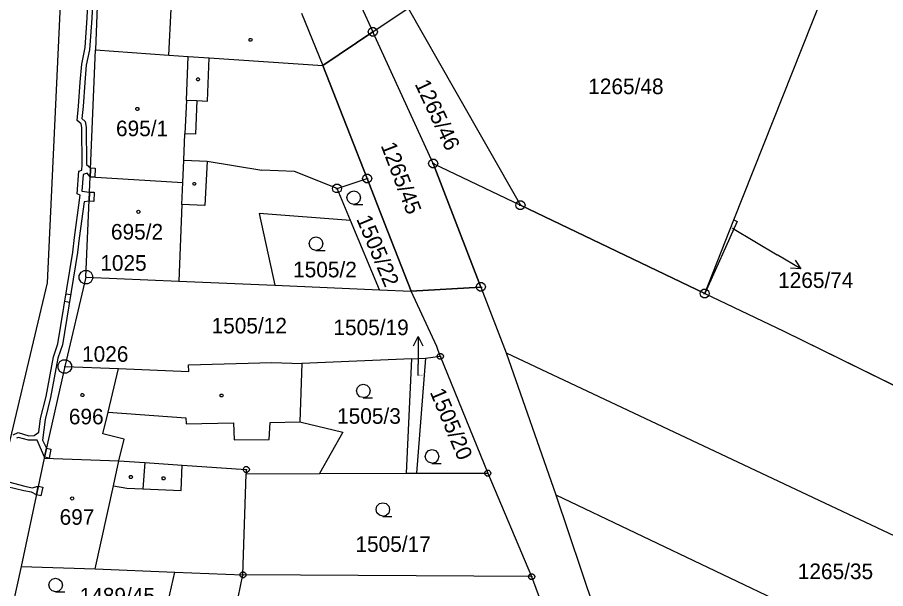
# Model space of a CAD drawing. Extents: x -779618 to -776429, y -1144546 to -1143350.
# Drawn here: x -777317.2 to -777222.5, y -1143978.4 to -1143916.1 of the extents above; entities that cross this region are included whole.
import ezdxf

# ---------------------------------------------------------------- set-up
doc = ezdxf.new("R2010")
doc.units = 0
for name, color, linetype in [('1', 7, 'Continuous'), ('11', 7, 'Continuous'), ('12', 7, 'Continuous'), ('13', 7, 'Continuous'), ('2', 7, 'Continuous'), ('3', 7, 'Continuous'), ('4', 7, 'Continuous'), ('5', 7, 'Continuous'), ('7', 7, 'Continuous'), ('8', 7, 'Continuous')]:
    doc.layers.add(name, color=color, linetype=linetype)

msp = doc.modelspace()

# ---------------------------------------------------------------- linework, layer by layer
at = {"layer": '1'}
for p, q in [((-777311.09, -1143883.18), (-777313.96, -1143945.06)), ((-777307.94, -1143898.78), (-777308.68, -1143919.63)), ((-777239.05, -1143938.18), (-777226.25, -1143905.92)), ((-777279.72, -1143914.89), (-777278.44, -1143917.67)), ((-777278.44, -1143917.67), (-777274.6, -1143915.07)), ((-777286.22, -1143915.64), (-777283.88, -1143921.35)), ((-777283.88, -1143921.35), (-777278.44, -1143917.67)), ((-777271.84, -1143932.03), (-777278.44, -1143917.67)), ((-777309.27, -1143933.48), (-777308.68, -1143919.63)), ((-777308.68, -1143919.63), (-777300.69, -1143920.2)), ((-777300.69, -1143920.2), (-777298.57, -1143920.35)), ((-777298.57, -1143920.35), (-777296.28, -1143920.51)), ((-777296.28, -1143920.51), (-777283.88, -1143921.35)), ((-777279.06, -1143933.68), (-777283.88, -1143921.35)), ((-777299.16, -1143934.11), (-777299.05, -1143931.67)), ((-777299.05, -1143931.67), (-777296.52, -1143931.78)), ((-777296.52, -1143931.78), (-777290.55, -1143932.77)), ((-777271.84, -1143932.03), (-777266.65, -1143945.51)), ((-777271.84, -1143932.03), (-777262.34, -1143936.58)), ((-777287, -1143932.91), (-777290.55, -1143932.77)), ((-777282.34, -1143934.75), (-777287, -1143932.91)), ((-777309.73, -1143944.43), (-777309.27, -1143933.48)), ((-777309.27, -1143933.48), (-777299.16, -1143934.11)), ((-777282.34, -1143934.75), (-777279.06, -1143933.68)), ((-777277.16, -1143938.54), (-777279.06, -1143933.68)), ((-777280.87, -1143938.26), (-777282.34, -1143934.75)), ((-777242.24, -1143946.21), (-777262.34, -1143936.58)), ((-777280.87, -1143938.26), (-777290.83, -1143937.5)), ((-777290.83, -1143937.5), (-777289.12, -1143945.32)), ((-777277.71, -1143945.82), (-777280.87, -1143938.26)), ((-777274.26, -1143945.97), (-777277.16, -1143938.54)), ((-777242.24, -1143946.21), (-777239.05, -1143938.18)), ((-777238.7, -1143938.36), (-777242.24, -1143946.21)), ((-777239.05, -1143938.18), (-777238.7, -1143938.36)), ((-777309.73, -1143944.43), (-777312.04, -1143954.18)), ((-777309.73, -1143944.43), (-777299.61, -1143944.86)), ((-777313.96, -1143945.06), (-777339.24, -1144051.23)), ((-777299.61, -1143944.86), (-777289.12, -1143945.32)), ((-777289.12, -1143945.32), (-777277.71, -1143945.82)), ((-777277.71, -1143945.82), (-777274.26, -1143945.97)), ((-777266.65, -1143945.51), (-777274.26, -1143945.97)), ((-777271.45, -1143951.98), (-777274.26, -1143945.97)), ((-777266.65, -1143945.51), (-777263.88, -1143952.69)), ((-777242.24, -1143946.21), (-777233.61, -1143950.34)), ((-777233.61, -1143950.34), (-777182.11, -1143975.59)), ((-777271.08, -1143953.07), (-777271.45, -1143951.98)), ((-777272.69, -1143953.26), (-777271.08, -1143953.07)), ((-777271.08, -1143953.07), (-777265.9, -1143965.83)), ((-777263.88, -1143952.69), (-777214.44, -1143976.01)), ((-777263.88, -1143952.69), (-777258.48, -1143968.19)), ((-777298.53, -1143953.99), (-777289.46, -1143953.75)), ((-777298.52, -1143954.72), (-777298.53, -1143953.99)), ((-777289.46, -1143953.75), (-777286.17, -1143953.86)), ((-777286.17, -1143953.86), (-777286.39, -1143960.23)), ((-777274.18, -1143953.33), (-777286.17, -1143953.86)), ((-777274.76, -1143965.81), (-777274.18, -1143953.33)), ((-777274.18, -1143953.33), (-777272.69, -1143953.26)), ((-777272.69, -1143953.26), (-777273.69, -1143965.81)), ((-777312.04, -1143954.18), (-777314.28, -1143964.19)), ((-777312.04, -1143954.18), (-777306.18, -1143954.38)), ((-777306.18, -1143954.38), (-777298.52, -1143954.72)), ((-777286.39, -1143960.23), (-777281.7, -1143961.34)), ((-777281.7, -1143961.34), (-777284.26, -1143965.84)), ((-777314.28, -1143964.19), (-777316.81, -1143975.99)), ((-777314.28, -1143964.19), (-777306.13, -1143964.46)), ((-777306.13, -1143964.46), (-777303.32, -1143964.66)), ((-777303.32, -1143964.66), (-777299.23, -1143964.94)), ((-777299.23, -1143964.94), (-777292.24, -1143965.43)), ((-777292.6, -1143976.92), (-777292.26, -1143965.88)), ((-777292.24, -1143965.43), (-777292.26, -1143965.88)), ((-777292.26, -1143965.88), (-777284.26, -1143965.84)), ((-777284.26, -1143965.84), (-777274.76, -1143965.81)), ((-777274.76, -1143965.81), (-777273.69, -1143965.81)), ((-777273.69, -1143965.81), (-777265.9, -1143965.83)), ((-777265.9, -1143965.83), (-777261.12, -1143977.11)), ((-777258.48, -1143968.19), (-777252.93, -1143984.66)), ((-777258.48, -1143968.19), (-777214.18, -1143989.29)), ((-777316.81, -1143975.99), (-777318.94, -1143985.81)), ((-777316.81, -1143975.99), (-777308.74, -1143976.27)), ((-777308.74, -1143976.27), (-777300.05, -1143976.62)), ((-777301.46, -1143982.86), (-777300.05, -1143976.62)), ((-777300.05, -1143976.62), (-777292.6, -1143976.92)), ((-777295.44, -1143990.58), (-777292.6, -1143976.92)), ((-777261.12, -1143977.11), (-777292.6, -1143976.92)), ((-777261.12, -1143977.11), (-777252.26, -1144001.3))]:
    msp.add_line(p, q, dxfattribs=at)
msp.add_lwpolyline([(-777274.6, -1143915.07), (-777269.54, -1143923.97), (-777262.34, -1143936.58)], dxfattribs=at)
at = {"layer": '11'}
msp.add_lwpolyline([(-777279.72, -1143914.89), (-777278.44, -1143917.67), (-777283.88, -1143921.35), (-777279.06, -1143933.68), (-777277.16, -1143938.54), (-777274.26, -1143945.97), (-777266.65, -1143945.51), (-777271.84, -1143932.03), (-777262.34, -1143936.58), (-777242.24, -1143946.21), (-777233.61, -1143950.34), (-777182.11, -1143975.59)], dxfattribs=at)
at = {"layer": '12'}
for p, q in [((-777307.94, -1143898.78), (-777308.68, -1143919.63)), ((-777300.69, -1143920.2), (-777300.44, -1143915.2)), ((-777309.27, -1143933.48), (-777308.68, -1143919.63)), ((-777308.68, -1143919.63), (-777300.69, -1143920.2)), ((-777308.68, -1143919.63), (-777300.69, -1143920.2)), ((-777300.69, -1143920.2), (-777298.57, -1143920.35)), ((-777298.77, -1143925.12), (-777298.57, -1143920.35)), ((-777298.77, -1143925.12), (-777298.93, -1143928.78)), ((-777299.05, -1143931.67), (-777298.93, -1143928.78)), ((-777299.16, -1143934.11), (-777299.05, -1143931.67)), ((-777309.73, -1143944.43), (-777309.27, -1143933.48)), ((-777309.27, -1143933.48), (-777299.16, -1143934.11)), ((-777309.27, -1143933.48), (-777299.16, -1143934.11)), ((-777299.26, -1143936.5), (-777299.16, -1143934.11)), ((-777299.26, -1143936.5), (-777299.61, -1143944.86)), ((-777309.73, -1143944.43), (-777299.61, -1143944.86)), ((-777312.04, -1143954.18), (-777314.28, -1143964.19)), ((-777312.04, -1143954.18), (-777306.18, -1143954.38)), ((-777307.32, -1143959.16), (-777306.18, -1143954.38)), ((-777307.9, -1143961.52), (-777307.32, -1143959.16)), ((-777305.55, -1143962.1), (-777307.9, -1143961.52)), ((-777306.13, -1143964.46), (-777305.55, -1143962.1)), ((-777314.28, -1143964.19), (-777316.81, -1143975.99)), ((-777314.28, -1143964.19), (-777306.13, -1143964.46)), ((-777314.28, -1143964.19), (-777306.13, -1143964.46)), ((-777306.74, -1143967.19), (-777306.13, -1143964.46)), ((-777308.74, -1143976.27), (-777306.74, -1143967.19)), ((-777316.81, -1143975.99), (-777308.74, -1143976.27))]:
    msp.add_line(p, q, dxfattribs=at)
at = {"layer": '13'}
for p, q in [((-777309.58, -1143916.13), (-777309.4, -1143912.32)), ((-777308.89, -1143912.05), (-777309.08, -1143916.17)), ((-777309.82, -1143919.36), (-777309.58, -1143916.13)), ((-777309.08, -1143916.17), (-777309.34, -1143919.62)), ((-777310.19, -1143921.2), (-777309.82, -1143919.36)), ((-777309.34, -1143919.62), (-777309.69, -1143921.28)), ((-777310.37, -1143923.15), (-777310.19, -1143921.2)), ((-777309.69, -1143921.28), (-777309.87, -1143923.19)), ((-777310.53, -1143925.77), (-777310.37, -1143923.15)), ((-777309.87, -1143923.19), (-777310.03, -1143925.81)), ((-777310.7, -1143927.33), (-777310.53, -1143925.77)), ((-777310.03, -1143925.81), (-777310.18, -1143927.11)), ((-777310.26, -1143927.69), (-777310.7, -1143927.33)), ((-777310.18, -1143927.11), (-777309.8, -1143927.43)), ((-777309.8, -1143927.43), (-777309.69, -1143928.07)), ((-777310.19, -1143928.11), (-777310.26, -1143927.69)), ((-777310.16, -1143932.19), (-777310.19, -1143928.11)), ((-777309.69, -1143928.07), (-777309.66, -1143932.14)), ((-777310.19, -1143932.75), (-777310.16, -1143932.19)), ((-777309.66, -1143932.14), (-777309.23, -1143932.5)), ((-777310.7, -1143935.35), (-777310.5, -1143932.86)), ((-777310.5, -1143932.86), (-777310.19, -1143932.75)), ((-777309.61, -1143933.07), (-777310.02, -1143933.22)), ((-777309.27, -1143933.48), (-777309.61, -1143933.07)), ((-777310.02, -1143933.22), (-777310.18, -1143935.03)), ((-777310.18, -1143935.03), (-777309.34, -1143935.14)), ((-777310.98, -1143940.1), (-777310.42, -1143936.02)), ((-777310.35, -1143935.5), (-777310.7, -1143935.35)), ((-777310.42, -1143936.02), (-777310.35, -1143935.5)), ((-777309.34, -1143935.14), (-777309.38, -1143936.14)), ((-777309.94, -1143936.22), (-777310.48, -1143940.16)), ((-777309.38, -1143936.14), (-777309.94, -1143936.22)), ((-777311.17, -1143941.69), (-777310.98, -1143940.1)), ((-777310.48, -1143940.16), (-777310.67, -1143941.75)), ((-777312.78, -1143951.69), (-777311.17, -1143941.69)), ((-777310.67, -1143941.75), (-777312.3, -1143951.81)), ((-777311.906, -1143946.26), (-777311.412, -1143946.339)), ((-777311.55, -1143947.179), (-777312.043, -1143947.099)), ((-777313.26, -1143953.14), (-777312.78, -1143951.69)), ((-777312.3, -1143951.81), (-777312.78, -1143953.26)), ((-777314.07, -1143957.47), (-777313.26, -1143953.14)), ((-777312.78, -1143953.26), (-777313.59, -1143957.57)), ((-777314.68, -1143959.85), (-777314.07, -1143957.47)), ((-777313.59, -1143957.57), (-777314.18, -1143959.95)), ((-777314.86, -1143961.34), (-777314.68, -1143959.85)), ((-777314.18, -1143959.95), (-777314.47, -1143962.23)), ((-777317.66, -1143961.63), (-777317.14, -1143961.38)), ((-777317.14, -1143961.38), (-777315.95, -1143961.73)), ((-777315.37, -1143961.72), (-777314.86, -1143961.34)), ((-777317.1, -1143961.92), (-777317.3, -1143962.01)), ((-777316.01, -1143962.23), (-777317.1, -1143961.92)), ((-777315.04, -1143962.22), (-777316.01, -1143962.23)), ((-777315.95, -1143961.73), (-777315.37, -1143961.72)), ((-777314.25, -1143964.07), (-777315.04, -1143962.22)), ((-777314.47, -1143962.23), (-777314.03, -1143963.09)), ((-777314.03, -1143963.09), (-777314.25, -1143964.07)), ((-777318.19, -1143966.75), (-777316.39, -1143967.25)), ((-777316.39, -1143967.25), (-777315.6, -1143967.41)), ((-777315.6, -1143967.41), (-777314.93, -1143967.22)), ((-777316.51, -1143967.73), (-777318.31, -1143967.3)), ((-777315.68, -1143967.91), (-777316.51, -1143967.73)), ((-777315.14, -1143968.2), (-777315.68, -1143967.91))]:
    msp.add_line(p, q, dxfattribs=at)
for points in [[(-777309.23, -1143932.5), (-777309.24, -1143932.76), (-777309.27, -1143933.48)], [(-777314.93, -1143967.22), (-777314.95, -1143967.31), (-777315.14, -1143968.2)]]:
    msp.add_lwpolyline(points, dxfattribs=at)
for points in [[(-777308.73, -1143932.52), (-777308.77, -1143933.51), (-777309.27, -1143933.48), (-777309.24, -1143932.76), (-777309.23, -1143932.5)], [(-777308.84, -1143935.16), (-777308.88, -1143936.16), (-777309.38, -1143936.14), (-777309.34, -1143935.14)], [(-777314.03, -1143963.09), (-777313.55, -1143963.2), (-777313.76, -1143964.17), (-777314.25, -1143964.07)], [(-777314.93, -1143967.22), (-777314.44, -1143967.33), (-777314.65, -1143968.31), (-777315.14, -1143968.2)]]:
    msp.add_lwpolyline(points, close=True, dxfattribs=at)
at = {"layer": '3'}
for points in [[(-777280.51, -1143936.49), (-777280.89, -1143936.39), (-777281.16, -1143936.12), (-777281.26, -1143935.75), (-777281.16, -1143935.38), (-777280.89, -1143935.11), (-777280.52, -1143935.01), (-777280.15, -1143935.11), (-777279.88, -1143935.38), (-777279.78, -1143935.76), (-777279.88, -1143936.14), (-777280.15, -1143936.41), (-777280.53, -1143936.51), (-777279.53, -1143936.51)], [(-777284.63, -1143941.51), (-777285.01, -1143941.41), (-777285.28, -1143941.14), (-777285.38, -1143940.77), (-777285.28, -1143940.4), (-777285.01, -1143940.13), (-777284.64, -1143940.03), (-777284.27, -1143940.13), (-777284, -1143940.4), (-777283.9, -1143940.78), (-777284, -1143941.16), (-777284.27, -1143941.43), (-777284.65, -1143941.53), (-777283.65, -1143941.53)], [(-777279.47, -1143957.58), (-777279.85, -1143957.48), (-777280.12, -1143957.21), (-777280.22, -1143956.84), (-777280.12, -1143956.47), (-777279.85, -1143956.2), (-777279.48, -1143956.1), (-777279.11, -1143956.2), (-777278.84, -1143956.47), (-777278.74, -1143956.85), (-777278.84, -1143957.23), (-777279.11, -1143957.5), (-777279.49, -1143957.6), (-777278.49, -1143957.6)], [(-777271.97, -1143964.73), (-777272.35, -1143964.63), (-777272.62, -1143964.36), (-777272.72, -1143963.99), (-777272.62, -1143963.62), (-777272.35, -1143963.35), (-777271.98, -1143963.25), (-777271.61, -1143963.35), (-777271.34, -1143963.62), (-777271.24, -1143964), (-777271.34, -1143964.38), (-777271.61, -1143964.65), (-777271.99, -1143964.75), (-777270.99, -1143964.75)], [(-777277.34, -1143970.52), (-777277.72, -1143970.42), (-777277.99, -1143970.15), (-777278.09, -1143969.78), (-777277.99, -1143969.41), (-777277.72, -1143969.14), (-777277.35, -1143969.04), (-777276.98, -1143969.14), (-777276.71, -1143969.41), (-777276.61, -1143969.79), (-777276.71, -1143970.17), (-777276.98, -1143970.44), (-777277.36, -1143970.54), (-777276.36, -1143970.54)], [(-777313.03, -1143978.76), (-777313.41, -1143978.66), (-777313.68, -1143978.39), (-777313.78, -1143978.02), (-777313.68, -1143977.65), (-777313.41, -1143977.38), (-777313.04, -1143977.28), (-777312.67, -1143977.38), (-777312.4, -1143977.65), (-777312.3, -1143978.03), (-777312.4, -1143978.41), (-777312.67, -1143978.68), (-777313.05, -1143978.78), (-777312.05, -1143978.78)]]:
    msp.add_lwpolyline(points, dxfattribs=at)
at = {"layer": '4'}
for p, q in [((-777300.69, -1143920.2), (-777300.44, -1143915.2)), ((-777298.77, -1143925.12), (-777298.57, -1143920.35)), ((-777296.46, -1143925.22), (-777296.28, -1143920.51)), ((-777298.77, -1143925.12), (-777298.93, -1143928.78)), ((-777298.77, -1143925.12), (-777297.62, -1143925.17)), ((-777297.62, -1143925.17), (-777297.77, -1143928.83)), ((-777297.62, -1143925.17), (-777296.46, -1143925.22)), ((-777299.05, -1143931.67), (-777298.93, -1143928.78)), ((-777297.77, -1143928.83), (-777298.93, -1143928.78)), ((-777296.52, -1143931.78), (-777296.78, -1143936.6)), ((-777299.26, -1143936.5), (-777299.16, -1143934.11)), ((-777299.26, -1143936.5), (-777299.61, -1143944.86)), ((-777296.78, -1143936.6), (-777299.26, -1143936.5)), ((-777307.32, -1143959.16), (-777306.18, -1143954.38)), ((-777307.9, -1143961.52), (-777307.32, -1143959.16)), ((-777307.32, -1143959.16), (-777298.83, -1143959.77)), ((-777298.83, -1143959.77), (-777298.81, -1143960.42)), ((-777298.81, -1143960.42), (-777293.64, -1143960.34)), ((-777293.64, -1143960.34), (-777293.58, -1143962.2)), ((-777289.73, -1143962.14), (-777289.65, -1143960.28)), ((-777289.65, -1143960.28), (-777286.39, -1143960.23)), ((-777305.55, -1143962.1), (-777307.9, -1143961.52)), ((-777306.13, -1143964.46), (-777305.55, -1143962.1)), ((-777293.58, -1143962.2), (-777289.73, -1143962.14)), ((-777306.74, -1143967.19), (-777306.13, -1143964.46)), ((-777303.32, -1143964.66), (-777303.54, -1143967.53)), ((-777299.34, -1143967.71), (-777299.23, -1143964.94)), ((-777308.74, -1143976.27), (-777306.74, -1143967.19)), ((-777306.74, -1143967.19), (-777305.28, -1143967.45)), ((-777305.28, -1143967.45), (-777303.54, -1143967.53)), ((-777303.54, -1143967.53), (-777299.34, -1143967.71))]:
    msp.add_line(p, q, dxfattribs=at)
at = {"layer": '5'}
for points in [[(-777291.68, -1143918.39), (-777291.59, -1143918.54), (-777291.68, -1143918.69), (-777291.86, -1143918.69), (-777291.95, -1143918.54), (-777291.86, -1143918.39)], [(-777297.42, -1143922.69), (-777297.33, -1143922.84), (-777297.42, -1143922.99), (-777297.6, -1143922.99), (-777297.69, -1143922.84), (-777297.6, -1143922.69)], [(-777304.13, -1143925.9), (-777304.03, -1143925.92), (-777303.98, -1143926.01), (-777303.96, -1143926.07), (-777303.98, -1143926.16), (-777304.06, -1143926.23), (-777304.13, -1143926.24), (-777304.22, -1143926.21), (-777304.28, -1143926.15), (-777304.3, -1143926.07), (-777304.28, -1143925.98), (-777304.2, -1143925.91)], [(-777297.82, -1143934.09), (-777297.73, -1143934.24), (-777297.82, -1143934.39), (-777298, -1143934.39), (-777298.09, -1143934.24), (-777298, -1143934.09)], [(-777304.01, -1143937.13), (-777303.91, -1143937.15), (-777303.86, -1143937.24), (-777303.84, -1143937.3), (-777303.86, -1143937.39), (-777303.94, -1143937.46), (-777304.01, -1143937.47), (-777304.1, -1143937.44), (-777304.16, -1143937.38), (-777304.18, -1143937.3), (-777304.16, -1143937.21), (-777304.08, -1143937.14)], [(-777310.12, -1143957.13), (-777310.02, -1143957.15), (-777309.97, -1143957.24), (-777309.95, -1143957.3), (-777309.97, -1143957.39), (-777310.05, -1143957.46), (-777310.12, -1143957.47), (-777310.21, -1143957.44), (-777310.27, -1143957.38), (-777310.29, -1143957.3), (-777310.27, -1143957.21), (-777310.19, -1143957.14)], [(-777294.84, -1143957.19), (-777294.75, -1143957.34), (-777294.84, -1143957.49), (-777295.02, -1143957.49), (-777295.11, -1143957.34), (-777295.02, -1143957.19)], [(-777304.73, -1143966.09), (-777304.64, -1143966.24), (-777304.73, -1143966.39), (-777304.91, -1143966.39), (-777305, -1143966.24), (-777304.91, -1143966.09)], [(-777301.18, -1143966.23), (-777301.09, -1143966.38), (-777301.18, -1143966.53), (-777301.36, -1143966.53), (-777301.45, -1143966.38), (-777301.36, -1143966.23)], [(-777311.23, -1143968.41), (-777311.13, -1143968.43), (-777311.08, -1143968.52), (-777311.06, -1143968.58), (-777311.08, -1143968.67), (-777311.16, -1143968.74), (-777311.23, -1143968.75), (-777311.32, -1143968.72), (-777311.38, -1143968.66), (-777311.4, -1143968.58), (-777311.38, -1143968.49), (-777311.3, -1143968.42)]]:
    msp.add_lwpolyline(points, close=True, dxfattribs=at)
at = {"layer": '7'}
for p, q in [((-777239.2, -1143939.1), (-777234.34, -1143941.99)), ((-777231.761, -1143943.523), (-777234.34, -1143941.99)), ((-777273.5, -1143950.91), (-777273.5, -1143953.91)), ((-777273.5, -1143955.17), (-777273.5, -1143953.91))]:
    msp.add_line(p, q, dxfattribs=at)
for points in [[(-777232.365, -1143942.582), (-777231.761, -1143943.523), (-777232.876, -1143943.442)], [(-777274, -1143951.91), (-777273.5, -1143950.91), (-777273, -1143951.91)]]:
    msp.add_lwpolyline(points, dxfattribs=at)
at = {"layer": '8'}
for p, q in [((-777278.56, -1143917.67), (-777278.32, -1143917.67)), ((-777271.96, -1143932.03), (-777271.72, -1143932.03)), ((-777279.18, -1143933.68), (-777278.94, -1143933.68)), ((-777282.46, -1143934.75), (-777282.22, -1143934.75)), ((-777262.46, -1143936.58), (-777262.22, -1143936.58)), ((-777309.78, -1143944.43), (-777309.68, -1143944.43)), ((-777266.77, -1143945.51), (-777266.53, -1143945.51)), ((-777242.36, -1143946.21), (-777242.12, -1143946.21)), ((-777271.16, -1143953.07), (-777271, -1143953.07)), ((-777312.09, -1143954.18), (-777311.99, -1143954.18)), ((-777292.32, -1143965.43), (-777292.16, -1143965.43)), ((-777265.98, -1143965.83), (-777265.82, -1143965.83)), ((-777292.68, -1143976.92), (-777292.52, -1143976.92)), ((-777261.2, -1143977.11), (-777261.04, -1143977.11))]:
    msp.add_line(p, q, dxfattribs=at)
for points in [[(-777278.29, -1143917.19), (-777278.04, -1143917.37), (-777277.94, -1143917.66), (-777278.04, -1143917.95), (-777278.29, -1143918.13), (-777278.6, -1143918.13), (-777278.85, -1143917.95), (-777278.95, -1143917.66), (-777278.85, -1143917.37), (-777278.6, -1143917.19)], [(-777271.69, -1143931.55), (-777271.44, -1143931.73), (-777271.34, -1143932.02), (-777271.44, -1143932.31), (-777271.69, -1143932.49), (-777272, -1143932.49), (-777272.25, -1143932.31), (-777272.35, -1143932.02), (-777272.25, -1143931.73), (-777272, -1143931.55)], [(-777278.91, -1143933.2), (-777278.66, -1143933.38), (-777278.56, -1143933.67), (-777278.66, -1143933.96), (-777278.91, -1143934.14), (-777279.22, -1143934.14), (-777279.47, -1143933.96), (-777279.57, -1143933.67), (-777279.47, -1143933.38), (-777279.22, -1143933.2)], [(-777282.19, -1143934.27), (-777281.94, -1143934.45), (-777281.84, -1143934.74), (-777281.94, -1143935.03), (-777282.19, -1143935.21), (-777282.5, -1143935.21), (-777282.75, -1143935.03), (-777282.85, -1143934.74), (-777282.75, -1143934.45), (-777282.5, -1143934.27)], [(-777262.19, -1143936.1), (-777261.94, -1143936.28), (-777261.84, -1143936.57), (-777261.94, -1143936.86), (-777262.19, -1143937.04), (-777262.5, -1143937.04), (-777262.75, -1143936.86), (-777262.85, -1143936.57), (-777262.75, -1143936.28), (-777262.5, -1143936.1)], [(-777309.54, -1143943.71), (-777309.2, -1143943.9), (-777309.01, -1143944.24), (-777309.01, -1143944.63), (-777309.2, -1143944.97), (-777309.54, -1143945.16), (-777309.93, -1143945.16), (-777310.27, -1143944.97), (-777310.46, -1143944.63), (-777310.46, -1143944.24), (-777310.27, -1143943.9), (-777309.93, -1143943.71)], [(-777266.5, -1143945.03), (-777266.25, -1143945.21), (-777266.15, -1143945.5), (-777266.25, -1143945.79), (-777266.5, -1143945.97), (-777266.81, -1143945.97), (-777267.06, -1143945.79), (-777267.16, -1143945.5), (-777267.06, -1143945.21), (-777266.81, -1143945.03)], [(-777242.09, -1143945.73), (-777241.84, -1143945.91), (-777241.74, -1143946.2), (-777241.84, -1143946.49), (-777242.09, -1143946.67), (-777242.4, -1143946.67), (-777242.65, -1143946.49), (-777242.75, -1143946.2), (-777242.65, -1143945.91), (-777242.4, -1143945.73)], [(-777270.979, -1143952.748), (-777270.812, -1143952.869), (-777270.745, -1143953.063), (-777270.812, -1143953.258), (-777270.979, -1143953.378), (-777271.187, -1143953.378), (-777271.355, -1143953.258), (-777271.422, -1143953.063), (-777271.355, -1143952.869), (-777271.187, -1143952.748)], [(-777311.85, -1143953.46), (-777311.51, -1143953.65), (-777311.32, -1143953.99), (-777311.32, -1143954.38), (-777311.51, -1143954.72), (-777311.85, -1143954.91), (-777312.24, -1143954.91), (-777312.58, -1143954.72), (-777312.77, -1143954.38), (-777312.77, -1143953.99), (-777312.58, -1143953.65), (-777312.24, -1143953.46)], [(-777292.14, -1143965.108), (-777291.972, -1143965.229), (-777291.905, -1143965.423), (-777291.972, -1143965.618), (-777292.14, -1143965.738), (-777292.347, -1143965.738), (-777292.515, -1143965.618), (-777292.582, -1143965.423), (-777292.515, -1143965.229), (-777292.347, -1143965.108)], [(-777265.799, -1143965.508), (-777265.632, -1143965.629), (-777265.565, -1143965.823), (-777265.632, -1143966.018), (-777265.799, -1143966.138), (-777266.007, -1143966.138), (-777266.175, -1143966.018), (-777266.242, -1143965.823), (-777266.175, -1143965.629), (-777266.007, -1143965.508)], [(-777292.499, -1143976.598), (-777292.332, -1143976.719), (-777292.265, -1143976.913), (-777292.332, -1143977.108), (-777292.499, -1143977.228), (-777292.707, -1143977.228), (-777292.875, -1143977.108), (-777292.942, -1143976.913), (-777292.875, -1143976.719), (-777292.707, -1143976.598)], [(-777261.019, -1143976.788), (-777260.852, -1143976.909), (-777260.785, -1143977.103), (-777260.852, -1143977.298), (-777261.019, -1143977.418), (-777261.227, -1143977.418), (-777261.395, -1143977.298), (-777261.462, -1143977.103), (-777261.395, -1143976.909), (-777261.227, -1143976.788)]]:
    msp.add_lwpolyline(points, close=True, dxfattribs=at)

# ---------------------------------------------------------------- texts
at = {"layer": '2'}
for s, height, p in [('1265/48', 1.7, (-777254.944, -1143924.46)), ('695/1', 1.7, (-777306.453, -1143929.05)), ('695/2', 1.7, (-777307.003, -1143940.33)), ('1505/2', 1.7, (-777287.137, -1143944.45)), ('1505/12', 1.7, (-777296.027, -1143950.57)), ('1505/19', 0.1, (-777273.477, -1143955.17)), ('1505/3', 1.7, (-777282.337, -1143960.43)), ('696', 1.7, (-777311.593, -1143960.49)), ('697', 1.7, (-777312.603, -1143971.45)), ('1505/17', 1.7, (-777280.337, -1143974.41)), ('1265/35', 1.7, (-777232.087, -1143977.38)), ('1489/45', 1.7, (-777310.417, -1143980.04))]:
    msp.add_text(s, height=height, dxfattribs=at).set_placement(p)
for s, height, rotation, p in [('1265/46', 1.7, 295.18786, (-777273.903, -1143923.345)), ('1265/45', 1.7, 290.94797, (-777277.6, -1143930.057)), ('1505/22', 1.7, 292.83873, (-777280.268, -1143938.072)), ('1265/74', 0.1, 72.88023, (-777239.249, -1143939.355)), ('1505/20', 1.7, 292.72414, (-777272.248, -1143956.972))]:
    msp.add_text(s, height=height, rotation=rotation, dxfattribs=at).set_placement(p)
at = {"layer": '7'}
for s, p in [('1265/74', (-777234.234, -1143945.61)), ('1505/19', (-777282.74, -1143950.76))]:
    msp.add_text(s, height=1.7, dxfattribs=at).set_placement(p)
at = {"layer": '8'}
for s, p in [('1025', (-777308.167, -1143943.73)), ('1026', (-777310.157, -1143953.67))]:
    msp.add_text(s, height=1.7, dxfattribs=at).set_placement(p)

doc.saveas('drawing.dxf')
